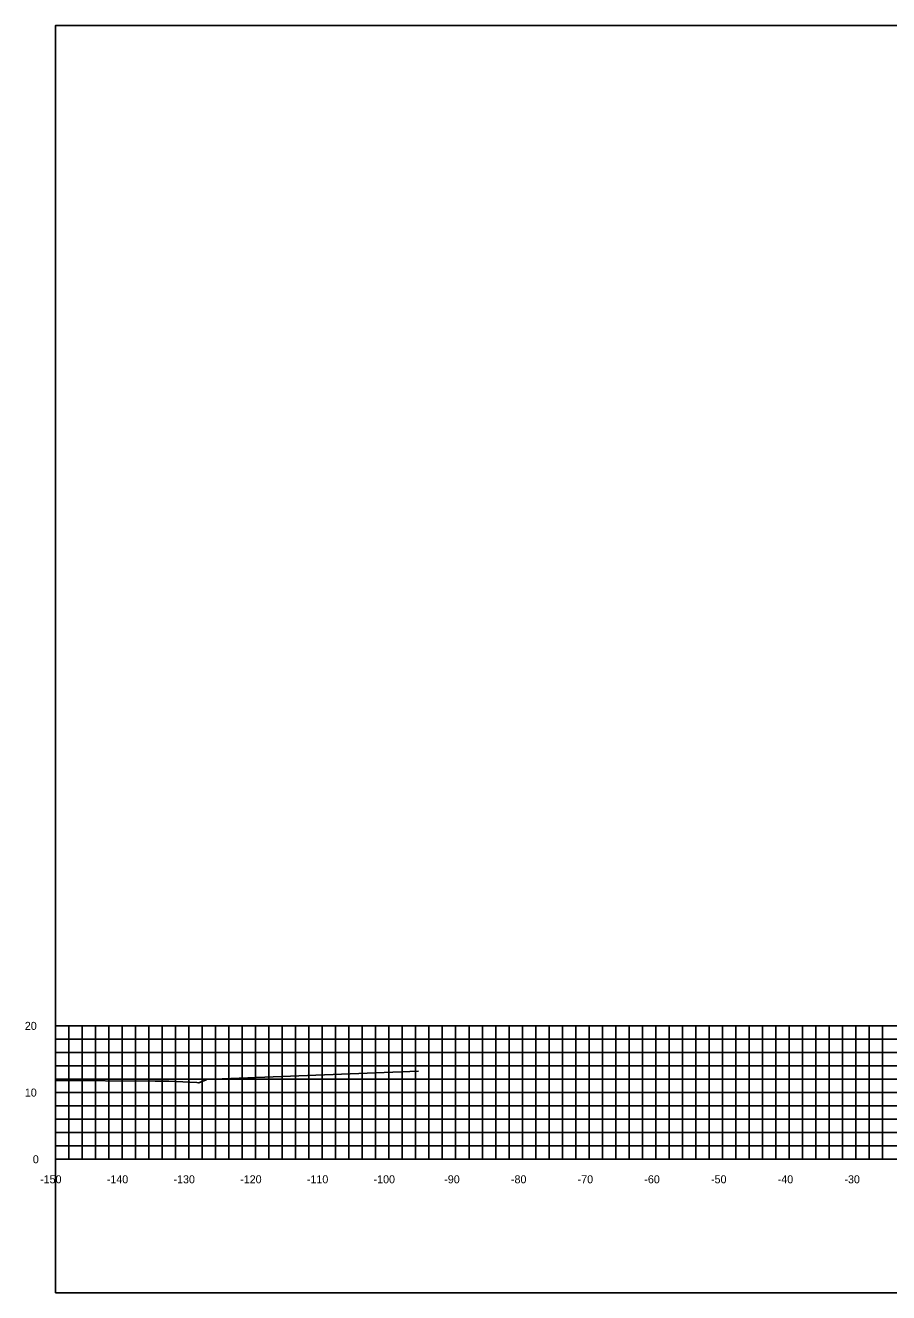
# Model space of a CAD drawing. Extents: x 1797759 to 1802785, y 249826 to 250371.
# Drawn here: x 1799841.7 to 1799971.1, y 249825.9 to 250015.9 of the extents above; entities that cross this region are included whole.
import ezdxf

# ---------------------------------------------------------------- set-up
doc = ezdxf.new("R2010")
doc.units = 0
for name, color, linetype in [('AXIS', 7, 'Continuous'), ('great seal', 7, 'Continuous'), ('Level 15', 7, 'Continuous'), ('Level 30', 7, 'Continuous'), ('Level 45', 7, 'Continuous'), ('Level 7', 7, 'Continuous')]:
    doc.layers.add(name, color=color, linetype=linetype)

msp = doc.modelspace()

# ---------------------------------------------------------------- linework, layer by layer
at = {"layer": 'AXIS'}
msp.add_lwpolyline([(1799846.22, 249825.85), (1800146.22, 249825.85), (1800146.22, 250015.85), (1799846.22, 250015.85)], close=True, dxfattribs=at)
at = {"layer": 'great seal'}
msp.add_lwpolyline([(1799846.22, 249857.66), (1799861.15, 249857.56), (1799862.66, 249857.55), (1799863.2, 249857.55), (1799867.42, 249857.34), (1799867.64, 249857.33), (1799867.69, 249857.33), (1799868.79, 249857.78), (1799868.86, 249857.82), (1799868.93, 249857.82), (1799869.98, 249857.86), (1799876.33, 249858.13), (1799900.63, 249859.07)], dxfattribs=at)
at = {"layer": 'Level 15'}
for p, q in [((1799846.22, 249865.85), (1800146.22, 249865.85)), ((1799846.22, 249845.85), (1799846.22, 249865.85)), ((1799848.22, 249845.85), (1799848.22, 249865.85)), ((1799850.22, 249845.85), (1799850.22, 249865.85)), ((1799852.22, 249845.85), (1799852.22, 249865.85)), ((1799854.22, 249845.85), (1799854.22, 249865.85)), ((1799856.22, 249845.85), (1799856.22, 249865.85)), ((1799858.22, 249845.85), (1799858.22, 249865.85)), ((1799860.22, 249845.85), (1799860.22, 249865.85)), ((1799862.22, 249845.85), (1799862.22, 249865.85)), ((1799864.22, 249845.85), (1799864.22, 249865.85)), ((1799866.22, 249845.85), (1799866.22, 249865.85)), ((1799868.22, 249845.85), (1799868.22, 249865.85)), ((1799870.22, 249845.85), (1799870.22, 249865.85)), ((1799872.22, 249845.85), (1799872.22, 249865.85)), ((1799874.22, 249845.85), (1799874.22, 249865.85)), ((1799876.22, 249845.85), (1799876.22, 249865.85)), ((1799878.22, 249845.85), (1799878.22, 249865.85)), ((1799880.22, 249845.85), (1799880.22, 249865.85)), ((1799882.22, 249845.85), (1799882.22, 249865.85)), ((1799884.22, 249845.85), (1799884.22, 249865.85)), ((1799886.22, 249845.85), (1799886.22, 249865.85)), ((1799888.22, 249845.85), (1799888.22, 249865.85)), ((1799890.22, 249845.85), (1799890.22, 249865.85)), ((1799892.22, 249845.85), (1799892.22, 249865.85)), ((1799894.22, 249845.85), (1799894.22, 249865.85)), ((1799896.22, 249845.85), (1799896.22, 249865.85)), ((1799898.22, 249845.85), (1799898.22, 249865.85)), ((1799900.22, 249845.85), (1799900.22, 249865.85)), ((1799902.22, 249845.85), (1799902.22, 249865.85)), ((1799904.22, 249845.85), (1799904.22, 249865.85)), ((1799906.22, 249845.85), (1799906.22, 249865.85)), ((1799908.22, 249845.85), (1799908.22, 249865.85)), ((1799910.22, 249845.85), (1799910.22, 249865.85)), ((1799912.22, 249845.85), (1799912.22, 249865.85)), ((1799914.22, 249845.85), (1799914.22, 249865.85)), ((1799916.22, 249845.85), (1799916.22, 249865.85)), ((1799918.22, 249845.85), (1799918.22, 249865.85)), ((1799920.22, 249845.85), (1799920.22, 249865.85)), ((1799922.22, 249845.85), (1799922.22, 249865.85)), ((1799924.22, 249845.85), (1799924.22, 249865.85)), ((1799926.22, 249845.85), (1799926.22, 249865.85)), ((1799928.22, 249845.85), (1799928.22, 249865.85)), ((1799930.22, 249845.85), (1799930.22, 249865.85)), ((1799932.22, 249845.85), (1799932.22, 249865.85)), ((1799934.22, 249845.85), (1799934.22, 249865.85)), ((1799936.22, 249845.85), (1799936.22, 249865.85)), ((1799938.22, 249845.85), (1799938.22, 249865.85)), ((1799940.22, 249845.85), (1799940.22, 249865.85)), ((1799942.22, 249845.85), (1799942.22, 249865.85)), ((1799944.22, 249845.85), (1799944.22, 249865.85)), ((1799946.22, 249845.85), (1799946.22, 249865.85)), ((1799948.22, 249845.85), (1799948.22, 249865.85)), ((1799950.22, 249845.85), (1799950.22, 249865.85)), ((1799952.22, 249845.85), (1799952.22, 249865.85)), ((1799954.22, 249845.85), (1799954.22, 249865.85)), ((1799956.22, 249845.85), (1799956.22, 249865.85)), ((1799958.22, 249845.85), (1799958.22, 249865.85)), ((1799960.22, 249845.85), (1799960.22, 249865.85)), ((1799962.22, 249845.85), (1799962.22, 249865.85)), ((1799964.22, 249845.85), (1799964.22, 249865.85)), ((1799966.22, 249845.85), (1799966.22, 249865.85)), ((1799968.22, 249845.85), (1799968.22, 249865.85)), ((1799970.22, 249845.85), (1799970.22, 249865.85)), ((1799846.22, 249863.85), (1800146.22, 249863.85)), ((1799846.22, 249861.85), (1800146.22, 249861.85)), ((1799846.22, 249859.85), (1800146.22, 249859.85)), ((1799846.22, 249857.85), (1800146.22, 249857.85)), ((1799846.22, 249855.85), (1800146.22, 249855.85)), ((1799846.22, 249853.85), (1800146.22, 249853.85)), ((1799846.22, 249851.85), (1800146.22, 249851.85)), ((1799846.22, 249849.85), (1800146.22, 249849.85)), ((1799846.22, 249847.85), (1800146.22, 249847.85)), ((1799846.22, 249845.85), (1800146.22, 249845.85))]:
    msp.add_line(p, q, dxfattribs=at)
at = {"layer": 'Level 30'}
for p, q in [((1799846.16, 249865.85), (1799846.22, 249865.85)), ((1799846.22, 249845.85), (1799846.22, 249865.85)), ((1799846.16, 249855.85), (1799846.22, 249855.85)), ((1799846.16, 249845.85), (1799846.22, 249845.85)), ((1799846.22, 249845.85), (1800146.22, 249845.85)), ((1799846.22, 249845.79), (1799846.22, 249845.85)), ((1799856.22, 249845.79), (1799856.22, 249845.85)), ((1799866.22, 249845.79), (1799866.22, 249845.85)), ((1799876.22, 249845.79), (1799876.22, 249845.85)), ((1799886.22, 249845.79), (1799886.22, 249845.85)), ((1799896.22, 249845.79), (1799896.22, 249845.85)), ((1799906.22, 249845.79), (1799906.22, 249845.85)), ((1799916.22, 249845.79), (1799916.22, 249845.85)), ((1799926.22, 249845.79), (1799926.22, 249845.85)), ((1799936.22, 249845.79), (1799936.22, 249845.85)), ((1799946.22, 249845.79), (1799946.22, 249845.85)), ((1799956.22, 249845.79), (1799956.22, 249845.85)), ((1799966.22, 249845.79), (1799966.22, 249845.85))]:
    msp.add_line(p, q, dxfattribs=at)

# ---------------------------------------------------------------- texts
msp.add_text('-', height=0.0001, dxfattribs=at).set_placement((1799846.22, 249845.85))
at = {"layer": 'Level 45'}
for s, p in [('-150', (1799843.91, 249842.25)), ('-140', (1799853.91, 249842.25)), ('-130', (1799863.91, 249842.25)), ('-120', (1799873.91, 249842.25)), ('-110', (1799883.91, 249842.25)), ('-100', (1799893.91, 249842.25)), ('-90', (1799904.51, 249842.25)), ('-80', (1799914.51, 249842.25)), ('-70', (1799924.51, 249842.25)), ('-60', (1799934.51, 249842.25)), ('-50', (1799944.51, 249842.25)), ('-40', (1799954.51, 249842.25)), ('-30', (1799964.51, 249842.25))]:
    msp.add_text(s, height=1.2, dxfattribs=at).set_placement(p)
at = {"layer": 'Level 7'}
for s, p in [('20', (1799841.62, 249865.25)), ('10', (1799841.62, 249855.25)), ('0', (1799842.82, 249845.25))]:
    msp.add_text(s, height=1.2, dxfattribs=at).set_placement(p)

doc.saveas('drawing.dxf')
